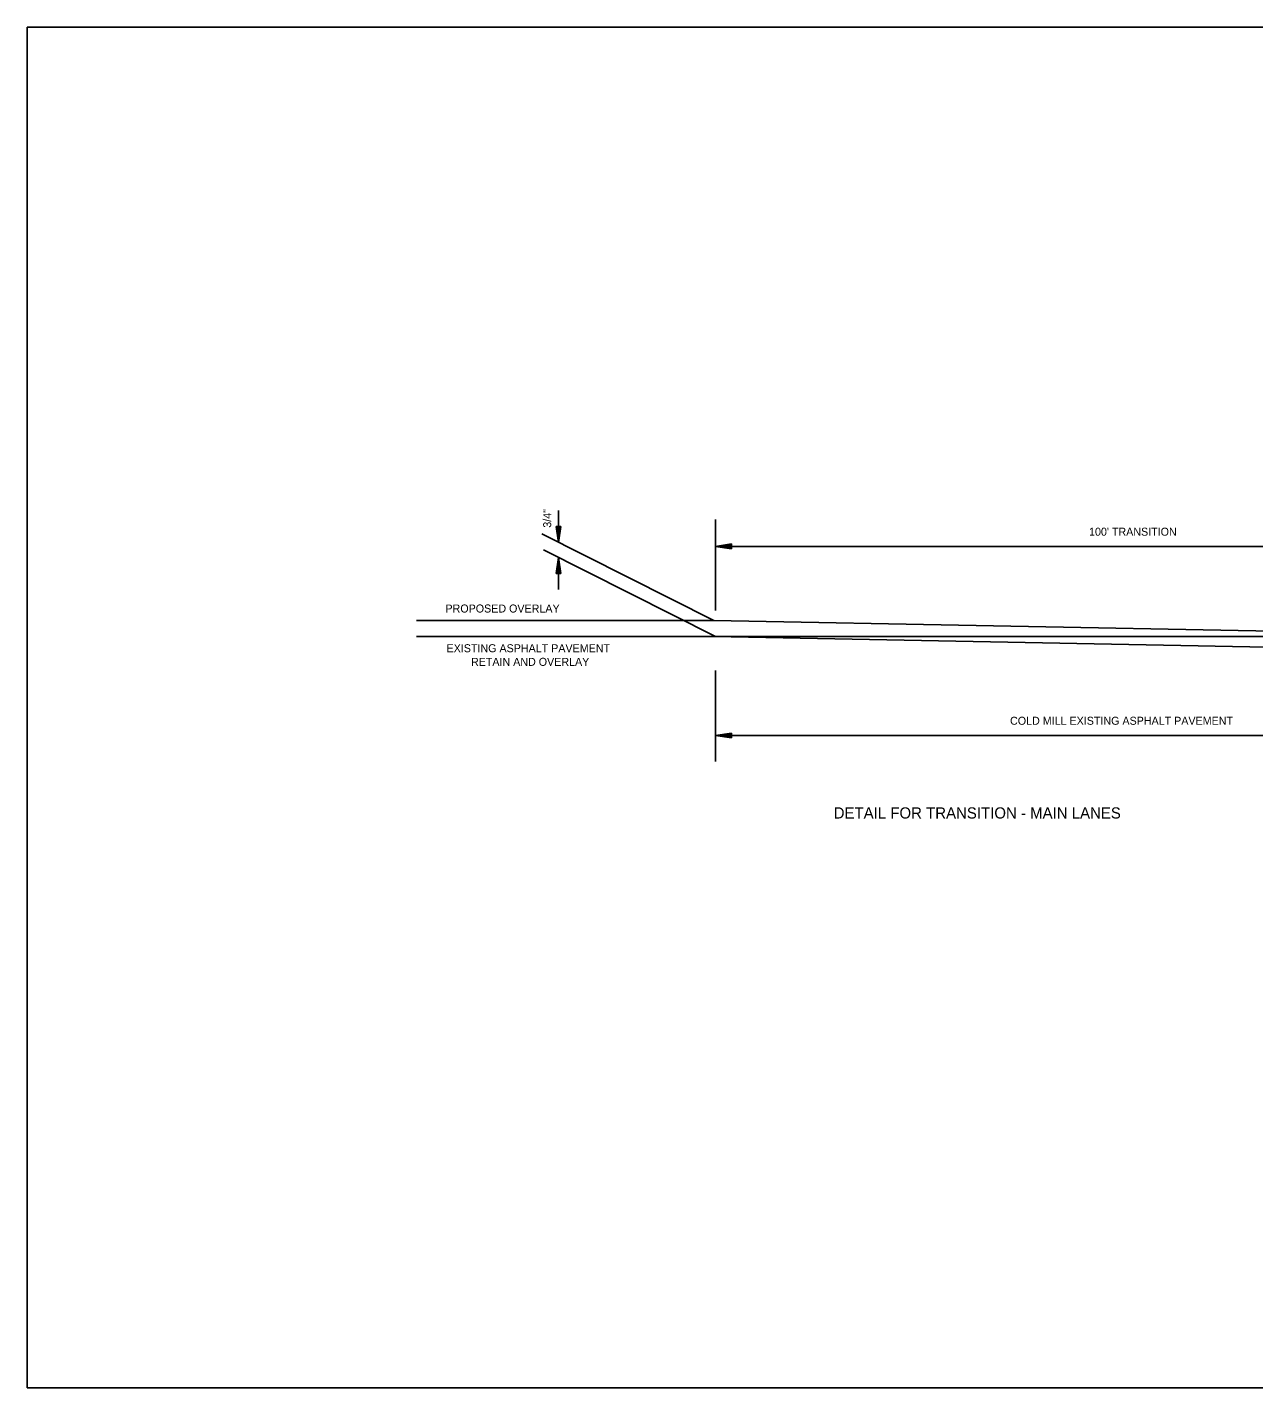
# Model space of a CAD drawing. Extents: x 8229 to 8749, y 14916 to 18021.
# Drawn here: x 8228.6 to 8530.9, y 14915.7 to 15251 of the extents above; entities that cross this region are included whole.
import ezdxf

# ---------------------------------------------------------------- set-up
doc = ezdxf.new("R2010")
doc.units = 0
for name, color, linetype in [('Default', 7, 'Continuous'), ('R_Draft', 7, 'Continuous'), ('R_Exist Surface', 7, 'Continuous')]:
    doc.layers.add(name, color=color, linetype=linetype)

msp = doc.modelspace()

# ---------------------------------------------------------------- linework, layer by layer
at = {"layer": 'Default'}
for points in [[(8746.76, 14915.68), (8746.76, 15250.96), (8228.6, 15250.96), (8228.6, 14915.68)], [(8228.6, 15250.96), (8228.6, 14915.68), (8746.76, 14915.68), (8746.76, 15250.96)]]:
    msp.add_lwpolyline(points, close=True, dxfattribs=at)
at = {"layer": 'R_Draft'}
for p, q in [((8358.95, 15127.96), (8359.54, 15124.01)), ((8360.13, 15127.96), (8358.95, 15127.96)), ((8359.05, 15127.96), (8359.54, 15124.67)), ((8359.15, 15127.96), (8359.54, 15125.35)), ((8359.25, 15127.96), (8359.54, 15126.01)), ((8359.35, 15127.96), (8359.54, 15126.67)), ((8359.45, 15127.96), (8359.54, 15127.33)), ((8360.13, 15127.96), (8359.54, 15124.01)), ((8359.73, 15127.96), (8359.54, 15126.67)), ((8359.93, 15127.96), (8359.54, 15125.35)), ((8360.03, 15127.96), (8359.54, 15124.67)), ((8359.84, 15127.96), (8359.54, 15126.01)), ((8359.63, 15127.96), (8359.54, 15127.33)), ((8402.17, 15123.62), (8398.22, 15123.02)), ((8402.17, 15122.43), (8398.22, 15123.02)), ((8402.17, 15123.52), (8398.88, 15123.02)), ((8402.17, 15122.53), (8398.88, 15123.02)), ((8402.17, 15123.42), (8399.56, 15123.02)), ((8402.17, 15122.63), (8399.56, 15123.02)), ((8402.17, 15123.32), (8400.22, 15123.02)), ((8402.17, 15122.73), (8400.22, 15123.02)), ((8402.17, 15123.22), (8400.88, 15123.02)), ((8402.17, 15122.83), (8400.88, 15123.02)), ((8402.17, 15123.12), (8401.54, 15123.02)), ((8402.17, 15122.93), (8401.54, 15123.02)), ((8402.17, 15122.43), (8402.17, 15123.62)), ((8358.95, 15116.35), (8359.54, 15120.29)), ((8359.05, 15116.35), (8359.54, 15119.63)), ((8359.15, 15116.35), (8359.54, 15118.96)), ((8359.25, 15116.35), (8359.54, 15118.3)), ((8360.13, 15116.35), (8359.54, 15120.29)), ((8360.03, 15116.35), (8359.54, 15119.63)), ((8359.93, 15116.35), (8359.54, 15118.96)), ((8359.84, 15116.35), (8359.54, 15118.3)), ((8358.95, 15116.35), (8360.13, 15116.35)), ((8359.35, 15116.35), (8359.54, 15117.63)), ((8359.45, 15116.35), (8359.54, 15116.97)), ((8359.73, 15116.35), (8359.54, 15117.63)), ((8359.63, 15116.35), (8359.54, 15116.97)), ((8402.17, 15077.02), (8398.22, 15076.43)), ((8402.17, 15075.84), (8398.22, 15076.43)), ((8402.17, 15076.93), (8398.88, 15076.43)), ((8402.17, 15075.94), (8398.88, 15076.43)), ((8402.17, 15076.83), (8399.56, 15076.43)), ((8402.17, 15076.04), (8399.56, 15076.43)), ((8402.17, 15076.73), (8400.22, 15076.43)), ((8402.17, 15076.14), (8400.22, 15076.43)), ((8402.17, 15076.63), (8400.88, 15076.43)), ((8402.17, 15076.24), (8400.88, 15076.43)), ((8402.17, 15076.53), (8401.54, 15076.43)), ((8402.17, 15076.34), (8401.54, 15076.43)), ((8402.17, 15075.84), (8402.17, 15077.02))]:
    msp.add_line(p, q, dxfattribs=at)
at = {"layer": 'R_Exist Surface'}
for p, q in [((8359.54, 15124.01), (8359.54, 15131.9)), ((8398.22, 15107.23), (8398.22, 15129.68)), ((8397.77, 15104.76), (8355.43, 15126.08)), ((8398.22, 15100.81), (8355.87, 15122.14)), ((8398.22, 15123.02), (8604.58, 15123.02)), ((8359.54, 15120.29), (8359.54, 15112.41)), ((8324.54, 15100.81), (8604.58, 15100.81)), ((8397.77, 15100.81), (8604.58, 15096.87)), ((8397.77, 15100.81), (8604.58, 15096.87)), ((8604.58, 15100.81), (8397.77, 15100.81)), ((8398.22, 15069.98), (8398.22, 15092.43)), ((8398.22, 15076.43), (8604.58, 15076.43))]:
    msp.add_line(p, q, dxfattribs=at)
msp.add_lwpolyline([(8324.54, 15104.76), (8397.77, 15104.76), (8604.58, 15100.81)], dxfattribs=at)

# ---------------------------------------------------------------- texts
msp.add_text('3/4"', height=1.972, rotation=90, dxfattribs=at).set_placement((8357.73, 15127.63))
for s, height, p in [("100' TRANSITION", 1.9719, (8490.28, 15125.66)), ('PROPOSED OVERLAY', 1.9719, (8331.67, 15106.73)), ('EXISTING ASPHALT PAVEMENT', 1.9719, (8331.94, 15096.94)), ('RETAIN AND OVERLAY', 1.9719, (8337.96, 15093.59)), ('COLD MILL EXISTING ASPHALT PAVEMENT', 1.9719, (8470.81, 15079.07)), ('DETAIL FOR TRANSITION - MAIN LANES', 2.7607, (8427.35, 15055.96))]:
    msp.add_text(s, height=height, dxfattribs=at).set_placement(p)

doc.saveas('drawing.dxf')
